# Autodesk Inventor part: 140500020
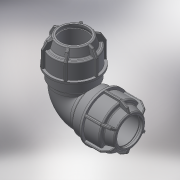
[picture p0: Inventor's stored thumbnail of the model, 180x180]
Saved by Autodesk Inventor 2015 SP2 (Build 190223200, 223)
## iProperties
Created: 2017-08
Part Number: 140500020
Material: Generic
Description: PLASSON L.14 90° ELBOW (SILVER) 20-20
Document SubType Name: Modeling
Designer: KIM
Density: 1 g/cm^3
Appearance: Default
Author: KIM
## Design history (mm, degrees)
derived "140500.ipt"
feature "Solid1::140500.ipt"
tag "TaggingFeature1"
body "Solid1"
other parameters: "d2" = 43, "d4" = 15 deg, "d5" = 28.38, "d6" = 9.3654, "d10" = 42, "d16" = 20.4, "d17" = 2.15, "d22" = 32, "d24" = 2.15, "d25" = 37.8, "d26" = 31.5, "d27" = 2.15, "d28" = 135 deg, "d29" = 1.29, "d31" = 1, "d46" = 150 deg, "d49" = 2.1, "d50" = 0, "d58" = 0.6, "d61" = 360 deg, "d63" = 18, "d80" = 28.8, "d81" = 1.6, "d84" = 2.15, "d112" = 57, "d113" = 2.28, "d115" = 90 deg, "E_" = 42, "A_" = 57, "l_" = 43
